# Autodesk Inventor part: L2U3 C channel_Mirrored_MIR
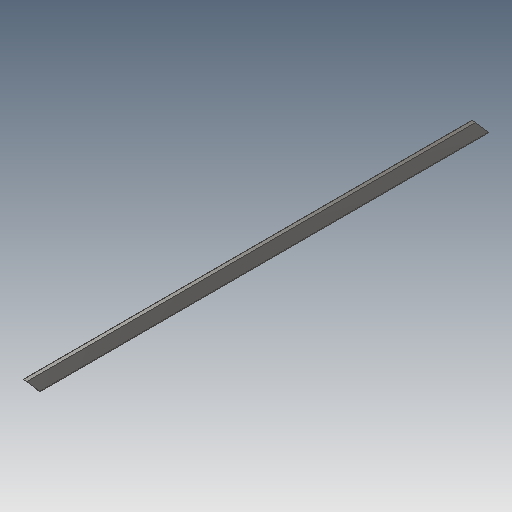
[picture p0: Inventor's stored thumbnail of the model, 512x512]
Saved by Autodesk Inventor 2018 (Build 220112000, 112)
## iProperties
Created: 2018-02
Part Number: L2U3 C channel_Mirrored_MIR
Material: Steel, Mild
Document SubType Name: Modeling
Designer: STK
Density: 7.85 g/cm^3
Appearance: Semi-Polished
Author: STK
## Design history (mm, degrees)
derived "L2U3 C channel_Mirrored.ipt"
feature "Solid1::L2U3 C channel_Mirrored.ipt" dims "d0" = 10
tag "TaggingFeature1"
body "Solid1"
